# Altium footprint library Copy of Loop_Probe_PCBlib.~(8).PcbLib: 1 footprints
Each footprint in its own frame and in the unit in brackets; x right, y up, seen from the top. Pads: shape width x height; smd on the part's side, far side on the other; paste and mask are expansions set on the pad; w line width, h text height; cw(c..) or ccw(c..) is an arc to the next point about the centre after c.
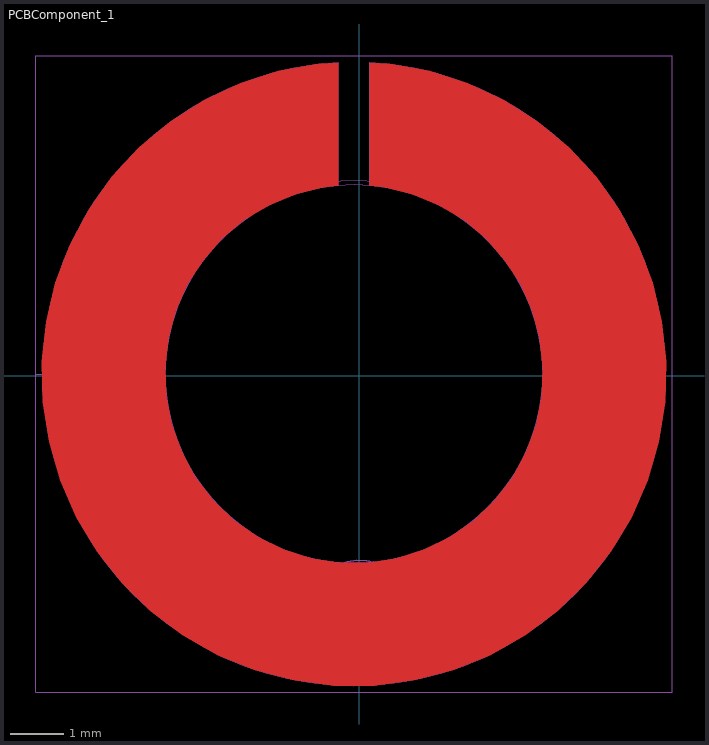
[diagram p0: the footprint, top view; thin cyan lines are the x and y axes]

## PCBComponent_1 [mil]
pads (2):
  round 1 on Mid1: 1(0.74,-181.37) 2(-65.31,-170.75)
GND 1:
  region: -15.44,232.28 -30.34,231.52 -59.7,226.2 -88.14,217.16 -115.17,204.53 -140.37,188.54 -163.29,169.45 -183.58,147.57 -200.89,123.26 -214.93,96.93 -225.48,69.02 -232.35,39.98 -235.43,10.3 -234.68,-19.53 -230.1,-49.01 -221.78,-77.67 -209.84,-105.01 -194.49,-130.6 -175.98,-154 -154.61,-174.83 -130.75,-192.75 -104.78,-207.45 -77.14,-218.7 -48.29,-226.3 -18.7,-230.13 11.14,-230.13 40.73,-226.3 69.59,-218.7 97.22,-207.45 123.19,-192.75 147.05,-174.83 168.42,-154 186.93,-130.6 202.28,-105.01 214.22,-77.67 222.54,-49.01 227.12,-19.53 227.87,10.3 224.79,39.98 217.92,69.02 207.37,96.93 193.33,123.26 176.02,147.57 155.74,169.45 132.81,188.54 107.62,204.53 80.58,217.16 52.14,226.2 22.78,231.52 7.88,232.28 7.88,141.13 18.54,139.83 39.39,134.81 59.23,126.68 77.61,115.61 94.08,101.88 108.28,85.8 119.85,67.74 128.54,48.14 134.15,27.43 136.53,6.12 135.64,-15.31 131.49,-36.36 124.19,-56.52 113.9,-75.34 100.86,-92.38 85.39,-107.22 67.83,-119.54 48.6,-129.04 28.14,-135.5 6.94,-138.76 -14.5,-138.76 -35.7,-135.5 -56.15,-129.04 -75.38,-119.54 -92.94,-107.22 -108.42,-92.38 -121.46,-75.34 -131.75,-56.52 -139.05,-36.36 -143.2,-15.31 -144.09,6.12 -141.7,27.43 -136.1,48.14 -127.41,67.74 -115.84,85.8 -101.64,101.88 -85.17,115.61 -66.79,126.68 -46.95,134.81 -26.09,139.83 -15.44,141.13
Loop Probe:
  circle w1: c0.74,-181.37 r14.26
  circle w1: c-65.31,-170.75 r9.18
  region: -74.49,-170.75 -74.49,-171.65 -74.13,-173.42 -73.44,-175.09 -72.44,-176.59 -71.16,-177.87 -69.66,-178.88 -67.99,-179.57 -66.21,-179.92 -65.31,-179.92 -64.41,-179.92 -62.63,-179.57 -60.96,-178.88 -59.46,-177.87 -58.18,-176.59 -57.18,-175.09 -56.49,-173.42 -56.13,-171.65 -56.13,-170.75 -56.13,-169.84 -56.49,-168.07 -57.18,-166.4 -58.18,-164.9 -59.46,-163.62 -60.96,-162.61 -62.63,-161.92 -64.41,-161.57 -65.31,-161.57 -66.21,-161.57 -67.99,-161.92 -69.66,-162.61 -71.16,-163.62 -72.44,-164.9 -73.44,-166.4 -74.13,-168.07 -74.49,-169.84
  region: -13.52,-181.37 -13.52,-182.77 -12.97,-185.52 -11.89,-188.12 -10.33,-190.46 -8.35,-192.44 -6.01,-194 -3.41,-195.08 -0.66,-195.63 0.74,-195.63 2.15,-195.63 4.9,-195.08 7.5,-194 9.84,-192.44 11.82,-190.46 13.38,-188.12 14.46,-185.52 15,-182.77 15,-181.37 15,-179.96 14.46,-177.21 13.38,-174.61 11.82,-172.28 9.84,-170.29 7.5,-168.73 4.9,-167.65 2.15,-167.11 0.74,-167.11 -0.66,-167.11 -3.41,-167.65 -6.01,-168.73 -8.35,-170.29 -10.33,-172.28 -11.89,-174.61 -12.97,-177.21 -13.52,-179.96
  lines w27.98: -65.31,-170.74 cw(c-3.78,1.22) 0.74,-181.37
GND 2:
  pour cut-out: 15.74,-181.37 15.74,-178.38 13.46,-172.87 9.24,-168.65 3.73,-166.37 0.74,-166.37 -2.24,-166.37 -7.75,-168.65 -11.97,-172.87 -14.26,-178.38 -14.26,-181.37 -14.26,-184.35 -11.97,-189.86 -7.75,-194.08 -2.24,-196.37 0.74,-196.37 3.68,-196.41 9.14,-194.24 13.35,-190.15 15.68,-184.76 15.72,-181.82
Mechanical 2:
  drawing of 580 lines, arcs and shapes, not listed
